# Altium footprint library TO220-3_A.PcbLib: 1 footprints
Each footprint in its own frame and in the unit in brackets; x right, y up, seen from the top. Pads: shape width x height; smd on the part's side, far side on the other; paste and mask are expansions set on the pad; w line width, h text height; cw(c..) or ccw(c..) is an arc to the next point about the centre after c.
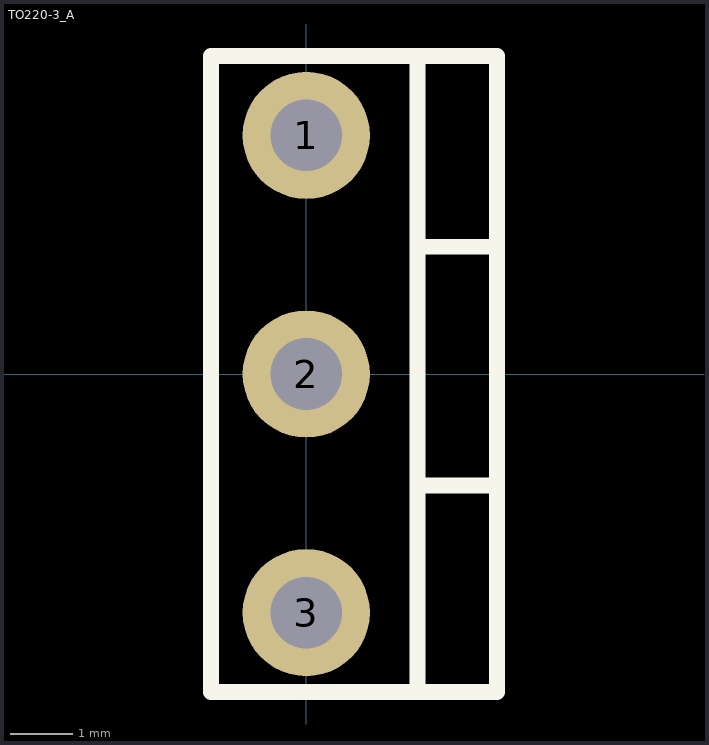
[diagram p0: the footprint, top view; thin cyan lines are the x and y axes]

## TO220-3_A [mil]
pads (3):
  round 80 hole 45: 1(0,150) 2(0,0) 3(0,-150)
Top Overlay:
  lines w10: 70,-200 70,200 ; 70,-70 120,-70 ; 70,80 120,80 ; -60,-200 -60,200 120,200 120,-200 -60,-200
